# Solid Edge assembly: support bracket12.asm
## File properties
Author: vicky raina
Template: normal.asm
Last saved by: Robert a Rhodes jr
Revision: 3
Application: Solid Edge
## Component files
adjusting_nut_handle.par
adjusting_screw_guide.par
Stock_support_base.par
thrust_bearing.par
adjusting_screw_nut.par
support_adjusting_screw.par
support_roller_bracket.par
stock_support_roller.par
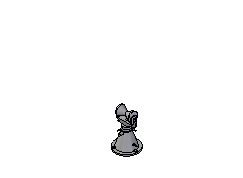
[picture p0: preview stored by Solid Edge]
